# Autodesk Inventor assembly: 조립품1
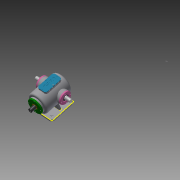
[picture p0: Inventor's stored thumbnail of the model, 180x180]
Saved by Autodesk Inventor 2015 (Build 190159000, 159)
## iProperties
Created: 2021-11
Part Number: 조립품1
Document SubType Name: Assembly
Designer: 1016549
Author: 1016549
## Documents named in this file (14)
- C:\Users\1016549\Desktop\711106V1044\조립품1.iam
- C:\Users\1016549\Desktop\711106V1044\베어링 6205.ipt
- 베어링 6205.ipt
- C:\Users\1016549\Desktop\711106V1044\본체.ipt
- C:\Users\1016549\Desktop\711106V1044\볼트 M4x0.7.ipt
- C:\Users\1016549\Desktop\711106V1044\부시.ipt
- C:\Users\1016549\Desktop\711106V1044\상부커버.ipt
- C:\Users\1016549\Desktop\711106V1044\슬라이드 커버.ipt
- C:\Users\1016549\Desktop\711106V1044\슬라이드.ipt
- C:\Users\1016549\Desktop\711106V1044\오일실.ipt
- 오일실.ipt
- C:\Users\1016549\Desktop\711106V1044\육각머리볼트 M4.ipt
- C:\Users\1016549\Desktop\711106V1044\축 커버.ipt
- C:\Users\1016549\Desktop\711106V1044\편심축.ipt
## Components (13 placed, 1 different names)
1. M4x0.7:13
2. M4x0.7:2
3. M4x0.7:3
4. M4x0.7:4
5. M4x0.7:5
6. M4x0.7:1
7. M4x0.7:6
8. M4x0.7:7
9. M4x0.7:8
10. M4x0.7:9
11. M4x0.7:10
12. M4x0.7:11
13. M4x0.7:12
